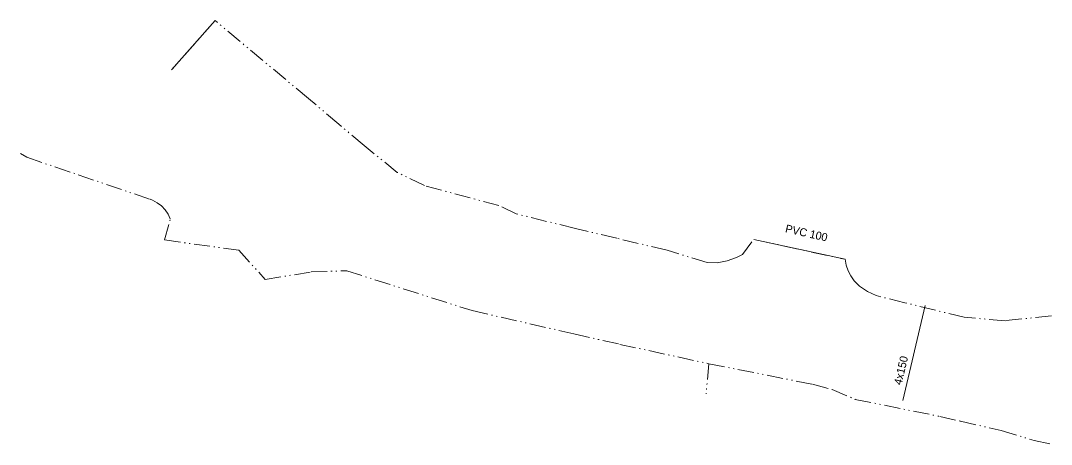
# Model space of a CAD drawing. Extents: x -642294 to -641980, y -1041631 to -1041422.
# Drawn here: x -642076.3 to -641979.7, y -1041630.7 to -1041591 of the extents above; entities that cross this region are included whole.
import ezdxf

# ---------------------------------------------------------------- set-up
doc = ezdxf.new("R2010")
doc.units = 0
doc.header["$LTSCALE"] = 0.3
doc.linetypes.add('DASH_DOUBLE_DOT', pattern=[9.2, 5, -1.2, 0.3, -1.2, 0.3, -1.2])
doc.layers.add('20', color=7, linetype='Continuous')
doc.layers.add('26', color=7, linetype='Continuous', lineweight=13)
doc.layers.add('36', color=7, linetype='DASH_DOUBLE_DOT', lineweight=13)

msp = doc.modelspace()

# ---------------------------------------------------------------- linework, layer by layer
at = {"layer": '26'}
for p, q in [((-642062.138, -1041595.58), (-642058.058, -1041590.981)), ((-642007.578, -1041611.46), (-641999.018, -1041613.33)), ((-641993.612, -1041626.553), (-641991.506, -1041617.667))]:
    msp.add_line(p, q, dxfattribs=at)
at = {"layer": '36'}
for p, q in [((-642046.472, -1041600.671), (-642049.308, -1041598.28)), ((-642044.098, -1041602.67), (-642046.472, -1041600.671)), ((-642076.288, -1041603.41), (-642075.708, -1041603.78)), ((-642040.988, -1041605.19), (-642044.098, -1041602.67)), ((-642075.708, -1041603.78), (-642070.882, -1041605.421)), ((-642070.882, -1041605.421), (-642064.148, -1041607.71)), ((-642038.448, -1041606.43), (-642040.988, -1041605.19)), ((-642062.788, -1041611.52), (-642062.258, -1041609.55)), ((-642008.628, -1041612.89), (-642007.578, -1041611.46)), ((-642007.578, -1041611.46), (-641999.018, -1041613.33)), ((-642011.938, -1041613.64), (-642015.688, -1041612.481)), ((-641979.678, -1041618.621), (-641984.018, -1041619.08)), ((-642011.778, -1041623.1), (-642002.058, -1041625.03)), ((-642002.058, -1041625.03), (-642000.228, -1041625.52)), ((-642000.228, -1041625.52), (-641998.058, -1041626.44)), ((-641981.298, -1041630.29), (-641979.678, -1041630.655))]:
    msp.add_line(p, q, dxfattribs=at)
for points in [[(-642049.308, -1041598.28), (-642058.058, -1041590.981), (-642062.138, -1041595.58)], [(-642015.688, -1041612.481), (-642020.404, -1041611.362), (-642024.288, -1041610.44), (-642029.838, -1041609.07), (-642031.458, -1041608.3), (-642038.448, -1041606.43)], [(-642062.258, -1041609.55), (-642062.467, -1041609.102), (-642062.745, -1041608.692), (-642063.086, -1041608.333), (-642063.479, -1041608.033), (-642063.916, -1041607.8), (-642064.148, -1041607.71)], [(-642062.788, -1041611.52), (-642055.838, -1041612.481), (-642053.368, -1041615.22), (-642049.058, -1041614.511), (-642045.728, -1041614.4), (-642033.968, -1041618.131), (-642024.435, -1041620.306), (-642020.118, -1041621.29), (-642011.778, -1041623.1), (-642012.048, -1041625.92)], [(-642011.938, -1041613.64), (-642010.995, -1041613.643), (-642010.066, -1041613.486), (-642009.176, -1041613.174), (-642008.628, -1041612.89)], [(-641999.018, -1041613.33), (-641998.915, -1041613.873), (-641998.734, -1041614.394), (-641998.48, -1041614.884), (-641998.158, -1041615.333), (-641997.775, -1041615.73), (-641997.658, -1041615.83)], [(-641997.658, -1041615.83), (-641996.918, -1041616.338), (-641996.099, -1041616.707), (-641995.648, -1041616.84)], [(-641984.018, -1041619.08), (-641987.838, -1041618.761), (-641993.406, -1041617.392), (-641995.648, -1041616.84)], [(-641998.058, -1041626.44), (-641990.138, -1041628.04), (-641988.211, -1041628.483), (-641984.388, -1041629.361), (-641981.298, -1041630.29)]]:
    msp.add_lwpolyline(points, dxfattribs=at)

# ---------------------------------------------------------------- texts
at = {"layer": '20'}
for s, rotation, p in [('PVC 100', 347.353, (-642004.673, -1041610.786)), ('4x150', 76.813, (-641993.725, -1041625.147))]:
    msp.add_text(s, height=0.75, rotation=rotation, dxfattribs=at).set_placement(p)

doc.saveas('drawing.dxf')
